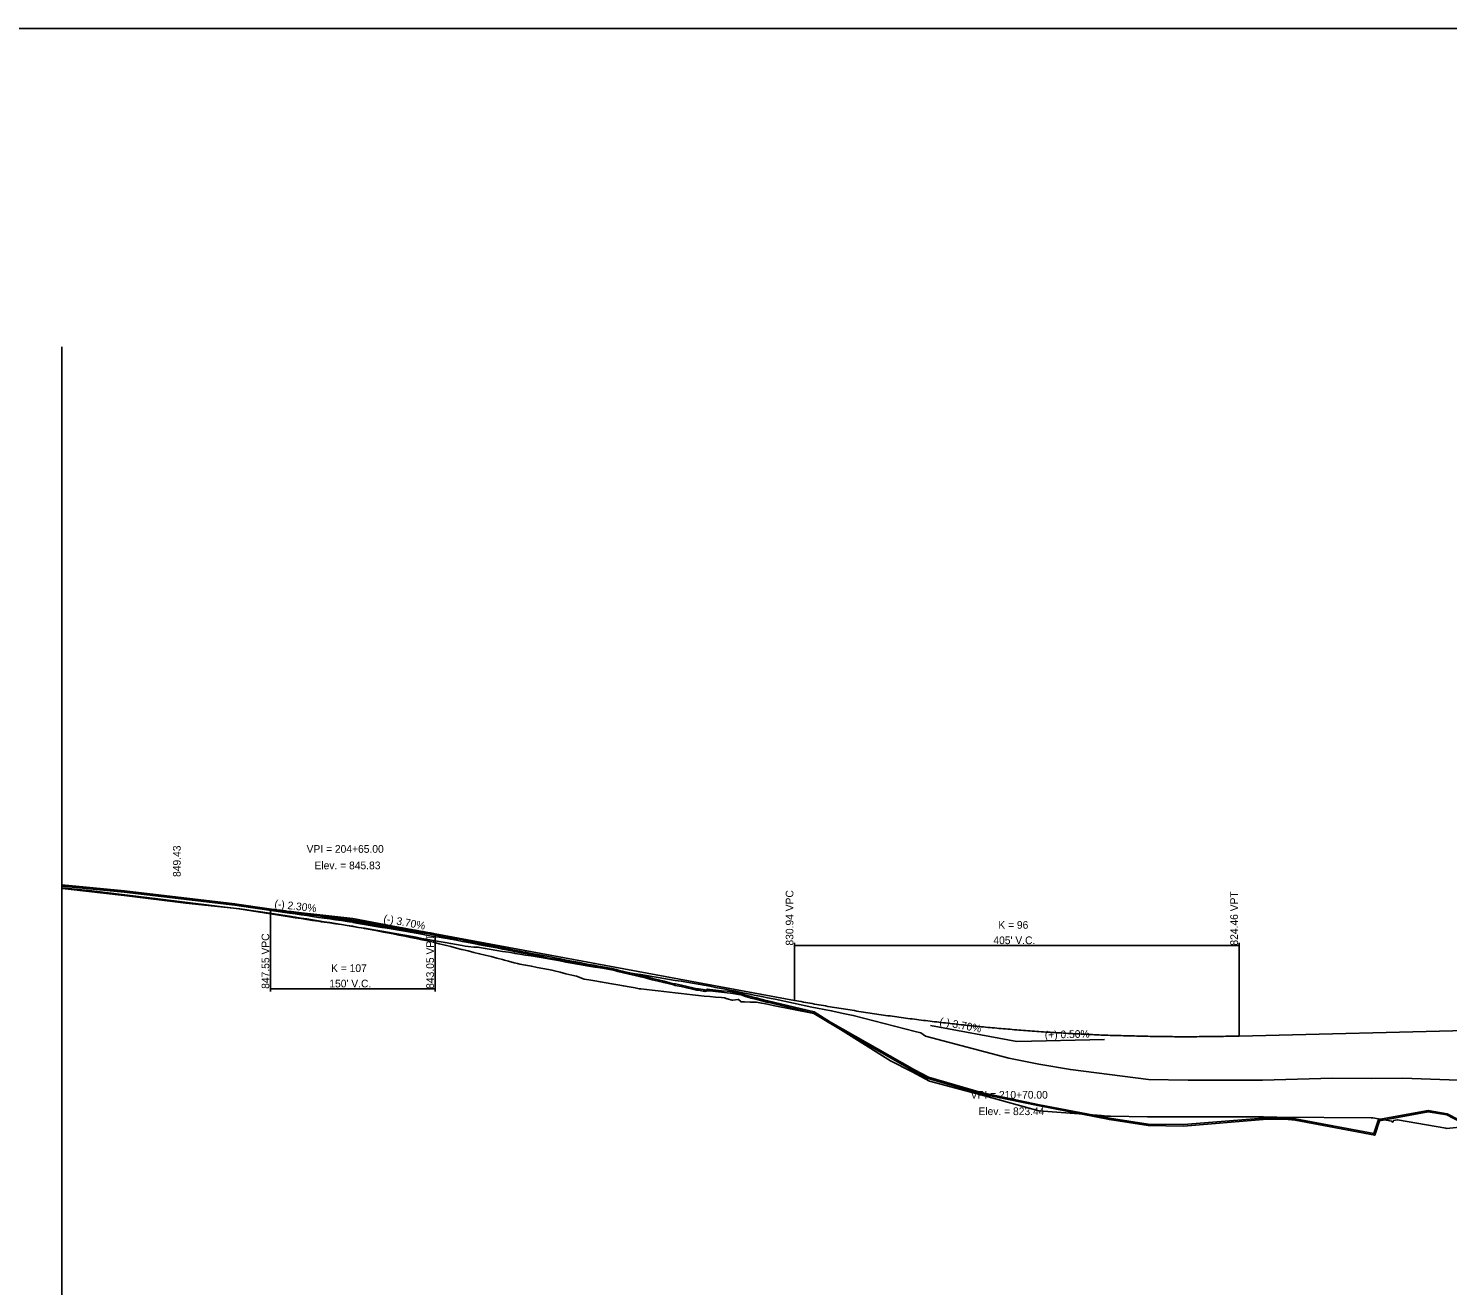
# Model space of a CAD drawing. Extents: x 1475855 to 1480900, y 1104511 to 1111511.
# Drawn here: x 1477333 to 1478626, y 1105656 to 1106801 of the extents above; entities that cross this region are included whole.
import ezdxf

# ---------------------------------------------------------------- set-up
doc = ezdxf.new("R2010")
doc.units = 0
for name, color, linetype in [('RD_DDB_GradeTX', 7, 'Continuous'), ('RD_DDB_Profile_EX', 7, 'Continuous'), ('RD_DDB_Profile_Lbl', 7, 'Continuous'), ('RD_DDB_Profile_PR', 7, 'Continuous'), ('RD_DDB_StripGrade', 7, 'Continuous'), ('RD_DDB_VCLbl', 7, 'Continuous'), ('RD_GPK_Profile_Cell', 7, 'Continuous'), ('RD_Sketch2', 7, 'Continuous'), ('RD_Sketch3', 7, 'Continuous'), ('RD_Sketch7', 7, 'Continuous'), ('RD_Sketch8', 7, 'Continuous')]:
    doc.layers.add(name, color=color, linetype=linetype)

msp = doc.modelspace()

# ---------------------------------------------------------------- linework, layer by layer
at = {"layer": 'RD_DDB_GradeTX'}
for p, q in [((1477549, 1105999.5), (1477628.5, 1105990.4)), ((1477707.1, 1105975.8), (1477628.5, 1105990.4)), ((1478154.8, 1105893), (1478233.5, 1105878.5)), ((1478313.4, 1105880.5), (1478233.5, 1105878.5))]:
    msp.add_line(p, q, dxfattribs=at)
at = {"layer": 'RD_DDB_Profile_EX'}
msp.add_lwpolyline([(1477363.5, 1106020), (1477420.4, 1106014.4), (1477521, 1106002.6), (1477525, 1106002.2), (1477571, 1105995.5), (1477576.2, 1105994.7), (1477581.5, 1105993.9), (1477586.7, 1105993.2), (1477592, 1105992.4), (1477597.2, 1105991.6), (1477602.5, 1105990.9), (1477607.7, 1105990.1), (1477612.9, 1105989.3), (1477618.2, 1105988.6), (1477623.4, 1105987.8), (1477625.6, 1105987.5), (1477628.2, 1105987.1), (1477628.7, 1105987), (1477633.9, 1105986.1), (1477639.2, 1105985.2), (1477644.4, 1105984.3), (1477649.7, 1105983.4), (1477654.9, 1105982.5), (1477660.1, 1105981.6), (1477665.4, 1105980.7), (1477670.6, 1105979.8), (1477675.9, 1105978.9), (1477681.1, 1105978), (1477686.4, 1105977.1), (1477691.6, 1105976.2), (1477696.9, 1105975.2), (1477702.1, 1105974.3), (1477707.4, 1105973.4), (1477712.3, 1105972.6), (1477712.6, 1105972.5), (1477717.8, 1105971.6), (1477723.1, 1105970.7), (1477728.3, 1105969.7), (1477730.2, 1105969.4), (1477733.6, 1105968.7), (1477738.8, 1105967.7), (1477744.1, 1105966.7), (1477749.3, 1105965.7), (1477754.6, 1105964.7), (1477759.8, 1105963.7), (1477765, 1105962.7), (1477770.3, 1105961.6), (1477775.5, 1105960.6), (1477780.8, 1105959.6), (1477783.4, 1105959.1), (1477786, 1105958.6), (1477791.3, 1105957.6), (1477796.5, 1105956.6), (1477801.8, 1105955.5), (1477807, 1105954.5), (1477812.3, 1105953.5), (1477817.5, 1105952.5), (1477822.7, 1105951.5), (1477828, 1105950.5), (1477833.2, 1105949.5), (1477836.5, 1105948.8), (1477838.5, 1105948.5), (1477843.7, 1105947.5), (1477848.2, 1105946.8), (1477849, 1105946.6), (1477854.2, 1105945.6), (1477859.5, 1105944.7), (1477864.3, 1105943.8), (1477864.7, 1105943.7), (1477868.1, 1105942.8), (1477869.9, 1105942.4), (1477875.2, 1105941.1), (1477880.4, 1105939.9), (1477885.7, 1105938.6), (1477890.9, 1105937.3), (1477893.6, 1105936.7), (1477896.2, 1105936.1), (1477901.4, 1105934.8), (1477906.7, 1105933.5), (1477911.9, 1105932.2), (1477917.2, 1105930.9), (1477920.9, 1105930), (1477922.4, 1105929.6), (1477927.6, 1105928.5), (1477932.9, 1105927.3), (1477938.1, 1105926.2), (1477941.8, 1105925.4), (1477943.4, 1105925.2), (1477947.7, 1105924.5), (1477948.6, 1105924.3), (1477949.7, 1105924.1), (1477952, 1105924.8), (1477953.9, 1105924.6), (1477959.1, 1105924.1), (1477964.4, 1105923.6), (1477969.6, 1105923), (1477972.8, 1105922.7), (1477974.8, 1105922.3), (1477980.1, 1105921.3), (1477982.4, 1105920.9), (1477985.3, 1105919.9), (1477990.6, 1105918.2), (1477990.9, 1105918.1), (1477992.7, 1105917.8), (1477995.8, 1105917), (1478001.1, 1105915.7), (1478005.8, 1105914.5), (1478006.3, 1105914.4), (1478011.6, 1105913.1), (1478048.4, 1105904.3), (1478063.1, 1105895.1), (1478139.8, 1105851.5), (1478152.7, 1105844.8), (1478200.9, 1105830.8), (1478252.6, 1105820.1), (1478317.9, 1105807.4), (1478353.1, 1105802), (1478385.5, 1105801.5), (1478457.9, 1105807.6), (1478477.6, 1105807.9), (1478487.1, 1105806.8), (1478559.6, 1105793.2), (1478564.1, 1105806.4), (1478608.4, 1105814.5), (1478625.2, 1105811.6), (1478657.2, 1105795)], dxfattribs=at)
at = {"layer": 'RD_DDB_Profile_PR'}
for p, q in [((1477471.8, 1106008.4), (1477553.5, 1105999)), ((1477703.5, 1105976.5), (1478031, 1105915.9)), ((1478436, 1105883.5), (1478716, 1105890.5))]:
    msp.add_line(p, q, dxfattribs=at)
for points in [[(1477553.5, 1105999), (1477556.5, 1105998.7), (1477559.5, 1105998.3), (1477562.5, 1105998), (1477565.5, 1105997.6), (1477568.5, 1105997.2), (1477571.5, 1105996.9), (1477574.5, 1105996.5), (1477577.5, 1105996.1), (1477580.5, 1105995.7), (1477583.5, 1105995.4), (1477586.5, 1105995), (1477589.5, 1105994.6), (1477592.5, 1105994.2), (1477595.5, 1105993.8), (1477598.5, 1105993.4), (1477601.5, 1105993), (1477604.5, 1105992.5), (1477607.5, 1105992.1), (1477610.5, 1105991.7), (1477613.5, 1105991.3), (1477616.5, 1105990.8), (1477619.5, 1105990.4), (1477622.5, 1105990), (1477625.5, 1105989.5), (1477628.5, 1105989.1), (1477631.5, 1105988.6), (1477634.5, 1105988.2), (1477637.5, 1105987.7), (1477640.5, 1105987.2), (1477643.5, 1105986.8), (1477646.5, 1105986.3), (1477649.5, 1105985.8), (1477652.5, 1105985.3), (1477655.5, 1105984.9), (1477658.5, 1105984.4), (1477661.5, 1105983.9), (1477664.5, 1105983.4), (1477667.5, 1105982.9), (1477670.5, 1105982.4), (1477673.5, 1105981.9), (1477676.5, 1105981.3), (1477679.5, 1105980.8), (1477682.5, 1105980.3), (1477685.5, 1105979.8), (1477688.5, 1105979.2), (1477691.5, 1105978.7), (1477694.5, 1105978.2), (1477697.5, 1105977.6), (1477700.5, 1105977.1), (1477703.5, 1105976.5)], [(1478031, 1105915.9), (1478039.1, 1105914.5), (1478047.2, 1105913), (1478055.3, 1105911.6), (1478063.4, 1105910.2), (1478071.5, 1105908.9), (1478079.6, 1105907.6), (1478087.7, 1105906.3), (1478095.8, 1105905), (1478103.9, 1105903.8), (1478112, 1105902.6), (1478120.1, 1105901.5), (1478128.2, 1105900.4), (1478136.3, 1105899.3), (1478144.4, 1105898.3), (1478152.5, 1105897.3), (1478160.6, 1105896.3), (1478168.7, 1105895.4), (1478176.8, 1105894.5), (1478184.9, 1105893.6), (1478193, 1105892.8), (1478201.1, 1105892), (1478209.2, 1105891.2), (1478217.3, 1105890.5), (1478225.4, 1105889.8), (1478233.5, 1105889.1), (1478241.6, 1105888.5), (1478249.7, 1105887.9), (1478257.8, 1105887.3), (1478265.9, 1105886.8), (1478274, 1105886.3), (1478282.1, 1105885.8), (1478290.2, 1105885.4), (1478298.3, 1105885), (1478306.4, 1105884.6), (1478314.5, 1105884.3), (1478322.6, 1105884), (1478330.7, 1105883.8), (1478338.8, 1105883.6), (1478346.9, 1105883.4), (1478355, 1105883.2), (1478363.1, 1105883.1), (1478371.2, 1105883), (1478379.3, 1105882.9), (1478387.4, 1105882.9), (1478395.5, 1105882.9), (1478403.6, 1105883), (1478411.7, 1105883.1), (1478419.8, 1105883.2), (1478427.9, 1105883.3), (1478436, 1105883.5)]]:
    msp.add_spline(points, degree=3, dxfattribs=at)
at = {"layer": 'RD_DDB_VCLbl'}
for p, q in [((1477553.5, 1105924), (1477553.5, 1105999)), ((1477703.5, 1105924), (1477703.5, 1105976.5)), ((1478031, 1105968.4), (1478031, 1105915.9)), ((1478031, 1105965.9), (1478436, 1105965.9)), ((1478436, 1105968.4), (1478436, 1105883.5)), ((1477553.5, 1105926.5), (1477703.5, 1105926.5))]:
    msp.add_line(p, q, dxfattribs=at)
at = {"layer": 'RD_GPK_Profile_Cell'}
msp.add_line((1477363.5, 1105511.2), (1477363.5, 1106511.2), dxfattribs=at)
at = {"layer": 'RD_Sketch2'}
msp.add_lwpolyline([(1477363.5, 1106018.4), (1477390.8, 1106015.7), (1477420.9, 1106012.1), (1477453.4, 1106008.2), (1477524.9, 1105999.4), (1477571, 1105992.1), (1477576.2, 1105991.3), (1477581.5, 1105990.5), (1477586.7, 1105989.6), (1477592, 1105988.8), (1477597.2, 1105988), (1477599.8, 1105987.6), (1477602.5, 1105987.2), (1477607.7, 1105986.5), (1477612.9, 1105985.7), (1477618.2, 1105985), (1477623.4, 1105984.2), (1477628.2, 1105983.5), (1477628.7, 1105983.5), (1477633.9, 1105982.5), (1477639.2, 1105981.6), (1477644.4, 1105980.7), (1477649.7, 1105979.8), (1477654.9, 1105978.9), (1477660.1, 1105978), (1477665.4, 1105977.1), (1477670.6, 1105976.2), (1477675.9, 1105975.3), (1477681.2, 1105974.4), (1477686.4, 1105973.4), (1477691.6, 1105972.4), (1477696.9, 1105971.5), (1477702.1, 1105970.5), (1477707.4, 1105969.6), (1477712.6, 1105968.6), (1477717.8, 1105967.7), (1477723.1, 1105966.8), (1477728.3, 1105965.9), (1477730.9, 1105965.4), (1477733.6, 1105965.1), (1477738.8, 1105964.4), (1477739.9, 1105964.3), (1477742.8, 1105964.3), (1477744.1, 1105964.1), (1477749.3, 1105963.3), (1477754.6, 1105962.4), (1477759.8, 1105961.5), (1477765, 1105960.6), (1477770.3, 1105959.8), (1477775.5, 1105958.9), (1477776.6, 1105958.7), (1477780.8, 1105958.1), (1477786, 1105957.3), (1477791.3, 1105956.4), (1477796.5, 1105955.6), (1477801.9, 1105954.8), (1477807, 1105953.9), (1477812.3, 1105952.9), (1477817.5, 1105951.9), (1477822.7, 1105950.9), (1477828, 1105950), (1477833.2, 1105949), (1477835, 1105948.7), (1477838.5, 1105948.1), (1477843.7, 1105947.2), (1477849, 1105946.3), (1477854.2, 1105945.5), (1477859.5, 1105944.6), (1477864.7, 1105943.7), (1477869.9, 1105942.9), (1477875.2, 1105942), (1477880.4, 1105941.1), (1477885.7, 1105940.3), (1477890.9, 1105939.4), (1477896.2, 1105938.5), (1477901.4, 1105937.7), (1477906.7, 1105936.8), (1477911.9, 1105936), (1477917.2, 1105935.1), (1477922.4, 1105934.2), (1477927.6, 1105933.4), (1477932.9, 1105932.5), (1477938.1, 1105931.7), (1477940, 1105931.4), (1477943.4, 1105930.7), (1477948.6, 1105929.7), (1477953.9, 1105928.8), (1477959.1, 1105927.8), (1477964.4, 1105926.8), (1477969.6, 1105925.8), (1477974.8, 1105924.8), (1477975.9, 1105924.6), (1477980.1, 1105923.7), (1477985.3, 1105922.6), (1477990.6, 1105921.6), (1477991.6, 1105921.3), (1477995.8, 1105920.5), (1478001.1, 1105919.4), (1478006.3, 1105918.4), (1478011.6, 1105917.3), (1478013.3, 1105917), (1478046.8, 1105909.9), (1478051.7, 1105908.9), (1478064.5, 1105906.5), (1478071.4, 1105905), (1478075.4, 1105904.1), (1478084.6, 1105902.3), (1478141, 1105887.6), (1478146, 1105886.3), (1478150.3, 1105883.3), (1478226.4, 1105863.5), (1478253.5, 1105858), (1478282.3, 1105852.9), (1478353.5, 1105844), (1478389.8, 1105843.2), (1478457.4, 1105843.2), (1478521, 1105845), (1478556.7, 1105844.8), (1478584.8, 1105845.2), (1478635.9, 1105843.4)], dxfattribs=at)
at = {"layer": 'RD_Sketch3'}
msp.add_lwpolyline([(1477363.5, 1106018), (1477369.2, 1106017.4), (1477420.3, 1106011.6), (1477476.5, 1106004.5), (1477525.6, 1105999.4), (1477554.9, 1105995.1), (1477571, 1105992.6), (1477576.2, 1105991.8), (1477581.5, 1105990.9), (1477586.7, 1105990.1), (1477592, 1105989.3), (1477597.2, 1105988.5), (1477602.5, 1105987.6), (1477607.7, 1105986.8), (1477612.9, 1105985.9), (1477618.2, 1105985.1), (1477623.4, 1105984.3), (1477628.7, 1105983.4), (1477633.9, 1105982.4), (1477638.4, 1105981.6), (1477639.2, 1105981.4), (1477644.4, 1105980.5), (1477649.7, 1105979.5), (1477654.9, 1105978.5), (1477656.5, 1105978.2), (1477660.1, 1105977.5), (1477665.4, 1105976.5), (1477670.6, 1105975.5), (1477675.9, 1105974.4), (1477681.1, 1105973.3), (1477686.4, 1105972.3), (1477691.6, 1105971.2), (1477696.9, 1105970.1), (1477699.3, 1105969.6), (1477702.1, 1105968.9), (1477707.4, 1105967.6), (1477712.6, 1105966.2), (1477717.8, 1105964.9), (1477723.1, 1105963.5), (1477727.6, 1105962.3), (1477728.3, 1105962.2), (1477732.3, 1105961.4), (1477733.6, 1105961.1), (1477738.8, 1105959.7), (1477744.1, 1105958.4), (1477749.3, 1105957.1), (1477754.6, 1105955.8), (1477759.8, 1105954.4), (1477765, 1105953.1), (1477766.8, 1105952.6), (1477770.3, 1105951.7), (1477775.5, 1105950.3), (1477778.5, 1105949.5), (1477780.8, 1105949.1), (1477786, 1105948.1), (1477791.3, 1105947), (1477796.5, 1105946), (1477801.8, 1105945), (1477807, 1105944), (1477810, 1105943.5), (1477812.3, 1105942.9), (1477817.5, 1105941.6), (1477822.7, 1105940.3), (1477828, 1105939), (1477832.3, 1105937.9), (1477833.2, 1105937.6), (1477838.5, 1105935.7), (1477839.5, 1105935.4), (1477843.7, 1105934.6), (1477849, 1105933.7), (1477854.2, 1105932.8), (1477859.5, 1105931.9), (1477864.7, 1105931), (1477869.9, 1105930.1), (1477875.2, 1105929.1), (1477880.4, 1105928.2), (1477885.7, 1105927.3), (1477889.4, 1105926.6), (1477890.9, 1105926.4), (1477896.2, 1105925.8), (1477901.4, 1105925.2), (1477906.7, 1105924.6), (1477911.9, 1105924), (1477917.2, 1105923.4), (1477922.4, 1105922.8), (1477927.6, 1105922.2), (1477932.9, 1105921.6), (1477938.1, 1105921), (1477943.4, 1105920.4), (1477948.6, 1105919.9), (1477953.9, 1105919.4), (1477959.1, 1105918.9), (1477964.4, 1105918.5), (1477967.1, 1105918.2), (1477969.6, 1105917.5), (1477974.2, 1105916.1), (1477974.8, 1105916.2), (1477979.8, 1105916.9), (1477980.1, 1105916.7), (1477982.5, 1105914.7), (1477985.3, 1105914.6), (1477990.6, 1105914.5), (1477995.8, 1105914.4), (1477996.1, 1105914.4), (1478001.1, 1105913.4), (1478006.3, 1105912.4), (1478011.6, 1105911.3), (1478048.7, 1105903.9), (1478073, 1105889.6), (1478118.6, 1105861), (1478138.1, 1105850.8), (1478154, 1105842.5), (1478205.2, 1105828.6), (1478253.6, 1105815.5), (1478310.6, 1105811), (1478315.7, 1105810.6), (1478318.8, 1105810.6), (1478352.6, 1105810), (1478358.4, 1105810), (1478435.1, 1105809.9), (1478458.3, 1105809.8), (1478470.3, 1105809.7), (1478556.5, 1105809.1), (1478557.8, 1105809), (1478575.1, 1105806), (1478575.9, 1105805), (1478576.4, 1105805.5), (1478576.8, 1105806.6), (1478580.3, 1105807.3), (1478624.4, 1105799.6), (1478625, 1105799.3), (1478683.3, 1105805.1)], dxfattribs=at)
at = {"layer": 'RD_Sketch7'}
msp.add_lwpolyline([(1477173.9, 1105041.2), (1480053.9, 1105041.2), (1480053.9, 1106801.2), (1477173.9, 1106801.2)], close=True, dxfattribs=at)
at = {"layer": 'RD_Sketch8'}
msp.add_lwpolyline([(1477363.6, 1106021.3), (1477420.5, 1106015.7), (1477521.2, 1106003.9), (1477525.1, 1106003.4), (1477571.2, 1105996.7), (1477576.4, 1105995.9), (1477581.7, 1105995.2), (1477586.9, 1105994.4), (1477592.1, 1105993.6), (1477597.4, 1105992.9), (1477602.6, 1105992.1), (1477607.9, 1105991.3), (1477613.1, 1105990.6), (1477618.4, 1105989.8), (1477623.6, 1105989), (1477625.7, 1105988.7), (1477628.4, 1105988.3), (1477628.9, 1105988.2), (1477634.1, 1105987.3), (1477639.4, 1105986.4), (1477644.6, 1105985.5), (1477649.9, 1105984.6), (1477655.1, 1105983.7), (1477660.4, 1105982.8), (1477665.6, 1105981.9), (1477670.9, 1105981), (1477676.1, 1105980.1), (1477681.3, 1105979.2), (1477686.6, 1105978.3), (1477691.8, 1105977.4), (1477697.1, 1105976.5), (1477702.3, 1105975.6), (1477707.6, 1105974.7), (1477712.5, 1105973.8), (1477712.8, 1105973.7), (1477718.1, 1105972.8), (1477723.3, 1105971.9), (1477728.6, 1105971), (1477730.4, 1105970.6), (1477733.8, 1105970), (1477739.1, 1105969), (1477744.3, 1105967.9), (1477749.6, 1105966.9), (1477754.8, 1105965.9), (1477760, 1105964.9), (1477765.3, 1105963.9), (1477770.5, 1105962.9), (1477775.8, 1105961.8), (1477781, 1105960.8), (1477783.6, 1105960.3), (1477786.3, 1105959.8), (1477791.5, 1105958.8), (1477796.8, 1105957.8), (1477802, 1105956.8), (1477807.2, 1105955.8), (1477812.5, 1105954.8), (1477817.7, 1105953.7), (1477823, 1105952.7), (1477828.2, 1105951.7), (1477833.5, 1105950.7), (1477836.7, 1105950.1), (1477838.7, 1105949.7), (1477843.9, 1105948.8), (1477848.4, 1105948), (1477849.2, 1105947.8), (1477854.4, 1105946.9), (1477859.7, 1105945.9), (1477864.6, 1105945), (1477865, 1105944.9), (1477868.4, 1105944), (1477870.2, 1105943.6), (1477875.5, 1105942.3), (1477880.7, 1105941.1), (1477886, 1105939.8), (1477891.2, 1105938.5), (1477896.5, 1105937.3), (1477901.7, 1105936), (1477907, 1105934.7), (1477912.2, 1105933.4), (1477917.5, 1105932.1), (1477921.2, 1105931.2), (1477922.7, 1105930.9), (1477927.9, 1105929.7), (1477933.2, 1105928.6), (1477938.4, 1105927.4), (1477942, 1105926.6), (1477943.6, 1105926.4), (1477947.9, 1105925.8), (1477948.9, 1105925.6), (1477949.6, 1105925.4), (1477951.9, 1105926.1), (1477954, 1105925.9), (1477959.2, 1105925.3), (1477964.5, 1105924.8), (1477969.7, 1105924.3), (1477973, 1105924), (1477975.1, 1105923.6), (1477980.3, 1105922.6), (1477982.7, 1105922.1), (1477985.7, 1105921.1), (1477991, 1105919.4), (1477991.2, 1105919.4), (1477993, 1105919), (1477996.1, 1105918.2), (1478001.4, 1105916.9), (1478006.1, 1105915.7), (1478006.6, 1105915.6), (1478048.9, 1105905.4), (1478063.7, 1105896.2), (1478140.4, 1105852.6), (1478153.2, 1105846), (1478201.2, 1105832), (1478252.8, 1105821.3), (1478318.1, 1105808.6), (1478353.2, 1105803.3), (1478385.5, 1105802.8), (1478457.8, 1105808.8), (1478477.7, 1105809.1), (1478487.3, 1105808.1), (1478558.8, 1105794.6), (1478563.1, 1105807.5), (1478608.4, 1105815.8), (1478625.6, 1105812.8), (1478657.4, 1105796.3)], dxfattribs=at)

# ---------------------------------------------------------------- texts
at = {"layer": 'RD_DDB_GradeTX'}
for s, rotation, p in [('(-) 2.30%', 353.4398, (1477556.9, 1106000.6)), ('(-) 3.70%', 349.5188, (1477656.1, 1105987.3)), ('(-) 3.70%', 349.5188, (1478162.7, 1105893.6)), ('(+) 0.50%', 1.4321, (1478259.1, 1105881.1))]:
    msp.add_text(s, height=7, rotation=rotation, dxfattribs=at).set_placement(p)
at = {"layer": 'RD_DDB_Profile_Lbl'}
msp.add_text('849.43', height=7, rotation=90, dxfattribs=at).set_placement((1477471.8, 1106028.4))
for s, p in [('VPI = 204+65.00', (1477586.5, 1106050.4)), ('Elev. = 845.83', (1477593.7, 1106035.4)), ('VPI = 210+70.00', (1478191.5, 1105826.5)), ('Elev. = 823.44', (1478198.6, 1105811.5))]:
    msp.add_text(s, height=7, dxfattribs=at).set_placement(p)
at = {"layer": 'RD_DDB_StripGrade'}
for s, p in [('830.94 VPC', (1478030, 1105965.9)), ('824.46 VPT', (1478435, 1105965.9)), ('847.55 VPC', (1477552.5, 1105926.5)), ('843.05 VPT', (1477702.5, 1105926.5))]:
    msp.add_text(s, height=7, rotation=90, dxfattribs=at).set_placement(p)
at = {"layer": 'RD_DDB_VCLbl'}
for s, p in [('K = 96', (1478216.7, 1105981.2)), ("405' V.C.", (1478212.2, 1105967.2)), ('K = 107', (1477608.8, 1105941.8)), ("150' V.C.", (1477607.2, 1105927.8))]:
    msp.add_text(s, height=7, dxfattribs=at).set_placement(p)

doc.saveas('drawing.dxf')
